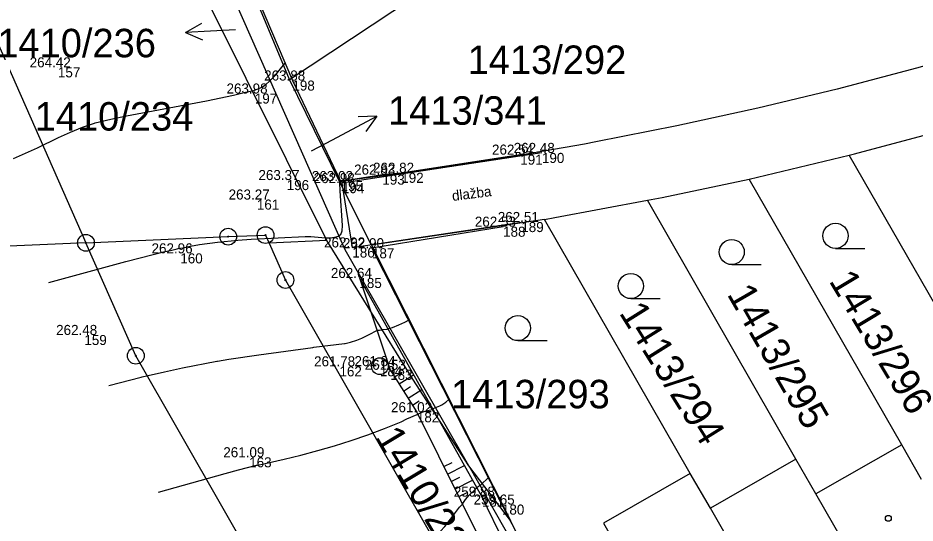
# Model space of a CAD drawing. Extents: x -771260 to -770828, y -1053564 to -1052811.
# Drawn here: x -770918.2 to -770864.6, y -1053347.8 to -1053317.7 of the extents above; entities that cross this region are included whole.
import ezdxf

# ---------------------------------------------------------------- set-up
doc = ezdxf.new("R2010")
doc.units = 0
for name, color, linetype in [('18_8_2023_dlazba', 7, 'Continuous'), ('18_8_2023_plot', 7, 'Continuous'), ('18_8_2023_popis_povrchu', 7, 'Continuous'), ('18_8_2023_sachta', 7, 'Continuous'), ('18_8_2023_ter_hrana', 7, 'Continuous'), ('18_8_2023_ter_pata', 7, 'Continuous'), ('18_8_2023_ter_srafa', 7, 'Continuous'), ('18_8_2023_vrstevnice_po_1m', 7, 'Continuous'), ('18_8_2023_vstup', 7, 'Continuous'), ('18_8_2023_zamereny_bod', 7, 'Continuous'), ('18_8_2023_zamereny_bod_cislo', 7, 'Continuous'), ('18_8_2023_zamereny_bod_vyska', 7, 'Continuous'), ('DKM_Hranice parcel', 7, 'Continuous'), ('DKM_Parcelní čísla', 7, 'Continuous'), ('DKM_Pop  PČ popisy', 7, 'Continuous'), ('DKM_Značky bodu BP', 7, 'Continuous'), ('DKM_Značky budov', 7, 'Continuous'), ('DKM_Značky kultur', 7, 'Continuous')]:
    doc.layers.add(name, color=color, linetype=linetype)

msp = doc.modelspace()

# ---------------------------------------------------------------- linework, layer by layer
at = {"layer": '18_8_2023_dlazba'}
for p, q in [((-770886.844, -1053325.753), (-770898.793, -1053327.556)), ((-770898.793, -1053327.556), (-770898.174, -1053331.397)), ((-770898.174, -1053331.397), (-770888.078, -1053329.878))]:
    msp.add_line(p, q, dxfattribs=at)
at = {"layer": '18_8_2023_plot'}
for p, q in [((-770906.001, -1053311.457), (-770901.756, -1053321.432)), ((-770901.756, -1053321.432), (-770898.876, -1053327.433)), ((-770895.251, -1053326.939), (-770888.14, -1053325.855)), ((-770898.876, -1053327.433), (-770896.381, -1053327.047)), ((-770889.166, -1053330.157), (-770897.001, -1053331.442)), ((-770897.001, -1053331.442), (-770889.236, -1053346.745)), ((-770889.236, -1053346.745), (-770886.57, -1053351.912))]:
    msp.add_line(p, q, dxfattribs=at)
at = {"layer": '18_8_2023_sachta'}
msp.add_circle((-770896.528, -1053338.484), 0.5, dxfattribs=at)
at = {"layer": '18_8_2023_ter_hrana'}
for p, q in [((-770897.752, -1053333.219), (-770895.914, -1053338.7)), ((-770895.914, -1053338.7), (-770894.318, -1053341.233)), ((-770894.318, -1053341.233), (-770889.903, -1053350.127))]:
    msp.add_line(p, q, dxfattribs=at)
at = {"layer": '18_8_2023_ter_pata'}
for p, q in [((-770890.436, -1053346.273), (-770897.752, -1053333.219)), ((-770887.502, -1053352.25), (-770890.436, -1053346.273))]:
    msp.add_line(p, q, dxfattribs=at)
at = {"layer": '18_8_2023_ter_srafa'}
for p, q in [((-770895.647, -1053339.123), (-770895.202, -1053338.842)), ((-770895.38, -1053339.546), (-770894.512, -1053338.998)), ((-770895.114, -1053339.969), (-770894.691, -1053339.702)), ((-770894.847, -1053340.392), (-770894.023, -1053339.872)), ((-770894.581, -1053340.815), (-770894.179, -1053340.562)), ((-770892.709, -1053344.474), (-770892.214, -1053344.228)), ((-770892.486, -1053344.921), (-770891.474, -1053344.419)), ((-770892.264, -1053345.369), (-770891.747, -1053345.112)), ((-770892.042, -1053345.817), (-770890.985, -1053345.292)), ((-770891.819, -1053346.265), (-770891.28, -1053345.997))]:
    msp.add_line(p, q, dxfattribs=at)
at = {"layer": '18_8_2023_vrstevnice_po_1m'}
for points in [[(-770918.418, -1053326.093), (-770916.989, -1053325.442), (-770915.723, -1053324.835), (-770915.014, -1053324.51), (-770914.29, -1053324.207), (-770913.573, -1053323.975), (-770913.53, -1053323.961), (-770912.601, -1053323.74), (-770911.658, -1053323.542), (-770906.885, -1053322.637), (-770905.279, -1053322.303), (-770904.551, -1053322.134), (-770904.054, -1053322.018), (-770904.016, -1053322.009), (-770903.792, -1053321.933), (-770903.577, -1053321.823), (-770903.37, -1053321.683), (-770903.105, -1053321.455), (-770902.944, -1053321.296), (-770902.789, -1053321.129), (-770902.382, -1053320.627), (-770902.196, -1053320.399), (-770902.166, -1053320.362)], [(-770902.166, -1053320.362), (-770902.166, -1053320.362)], [(-770902.166, -1053320.362), (-770902.166, -1053320.362)], [(-770902.944, -1053321.296), (-770902.944, -1053321.296)], [(-770902.789, -1053321.129), (-770902.789, -1053321.129)], [(-770903.577, -1053321.823), (-770903.577, -1053321.823)], [(-770903.37, -1053321.683), (-770903.37, -1053321.683)], [(-770903.105, -1053321.455), (-770903.105, -1053321.455)], [(-770905.279, -1053322.303), (-770905.279, -1053322.303)], [(-770904.016, -1053322.009), (-770904.016, -1053322.009)], [(-770903.792, -1053321.933), (-770903.792, -1053321.933)], [(-770906.885, -1053322.637), (-770906.885, -1053322.637)], [(-770913.53, -1053323.961), (-770913.53, -1053323.961)], [(-770912.601, -1053323.74), (-770912.601, -1053323.74)], [(-770911.658, -1053323.542), (-770911.658, -1053323.542)], [(-770915.014, -1053324.51), (-770915.014, -1053324.51)], [(-770914.29, -1053324.207), (-770914.29, -1053324.207)], [(-770915.723, -1053324.835), (-770915.723, -1053324.835)], [(-770916.989, -1053325.442), (-770916.989, -1053325.442)], [(-770916.308, -1053333.484), (-770911.709, -1053332.232), (-770910.077, -1053331.813), (-770909.381, -1053331.646), (-770909.044, -1053331.574), (-770908.962, -1053331.557), (-770908.632, -1053331.477), (-770908.586, -1053331.466), (-770908.295, -1053331.409), (-770907.864, -1053331.324), (-770907.844, -1053331.32), (-770907.303, -1053331.229), (-770906.237, -1053331.08), (-770905.015, -1053330.965), (-770904.21, -1053330.91), (-770900.991, -1053330.743), (-770900.922, -1053330.739), (-770900.661, -1053330.746), (-770899.782, -1053330.817), (-770899.448, -1053330.817), (-770899.35, -1053330.807), (-770899.27, -1053330.799), (-770899.024, -1053330.717), (-770898.908, -1053330.644), (-770898.87, -1053330.619), (-770898.775, -1053330.395), (-770898.769, -1053330.082), (-770898.909, -1053328.014), (-770898.929, -1053327.548), (-770898.931, -1053327.514), (-770898.901, -1053327.492), (-770898.846, -1053327.477), (-770898.802, -1053327.464), (-770898.657, -1053327.399), (-770898.562, -1053327.357)], [(-770898.931, -1053327.514), (-770898.931, -1053327.514)], [(-770898.901, -1053327.492), (-770898.901, -1053327.492)], [(-770898.802, -1053327.464), (-770898.802, -1053327.464)], [(-770898.909, -1053328.014), (-770898.909, -1053328.014)], [(-770898.775, -1053330.395), (-770898.775, -1053330.395)], [(-770898.769, -1053330.082), (-770898.769, -1053330.082)], [(-770905.015, -1053330.965), (-770905.015, -1053330.965)], [(-770904.21, -1053330.91), (-770904.21, -1053330.91)], [(-770900.922, -1053330.739), (-770900.922, -1053330.739)], [(-770900.661, -1053330.746), (-770900.661, -1053330.746)], [(-770899.782, -1053330.817), (-770899.782, -1053330.817)], [(-770899.448, -1053330.817), (-770899.448, -1053330.817)], [(-770899.27, -1053330.799), (-770899.27, -1053330.799)], [(-770899.024, -1053330.717), (-770899.024, -1053330.717)], [(-770898.87, -1053330.619), (-770898.87, -1053330.619)], [(-770908.586, -1053331.466), (-770908.586, -1053331.466)], [(-770907.864, -1053331.324), (-770907.864, -1053331.324)], [(-770907.303, -1053331.229), (-770907.303, -1053331.229)], [(-770906.237, -1053331.08), (-770906.237, -1053331.08)], [(-770910.077, -1053331.813), (-770910.077, -1053331.813)], [(-770909.381, -1053331.646), (-770909.381, -1053331.646)], [(-770908.962, -1053331.557), (-770908.962, -1053331.557)], [(-770911.709, -1053332.232), (-770911.709, -1053332.232)], [(-770916.308, -1053333.484), (-770916.308, -1053333.484)], [(-770912.725, -1053339.643), (-770910.784, -1053339.142), (-770910.728, -1053339.128), (-770909.401, -1053338.818), (-770908.314, -1053338.582), (-770906.273, -1053338.194), (-770906.234, -1053338.186), (-770905.55, -1053338.07), (-770903.757, -1053337.801), (-770900.54, -1053337.361), (-770900.476, -1053337.353), (-770898.633, -1053337.127), (-770898.609, -1053337.124), (-770898.286, -1053337.055), (-770897.896, -1053336.924), (-770897.616, -1053336.81), (-770897.169, -1053336.599), (-770896.7, -1053336.356), (-770896.664, -1053336.338), (-770896.547, -1053336.331), (-770896.43, -1053336.305), (-770896.389, -1053336.296), (-770896.096, -1053336.274), (-770896.049, -1053336.257), (-770896.008, -1053336.242), (-770895.782, -1053336.178), (-770895.388, -1053336.025), (-770895.044, -1053335.864), (-770895.006, -1053335.846), (-770894.823, -1053335.734), (-770894.787, -1053335.712)], [(-770894.787, -1053335.712), (-770894.787, -1053335.712)], [(-770894.787, -1053335.712), (-770894.787, -1053335.712)], [(-770896.664, -1053336.338), (-770896.664, -1053336.338)], [(-770896.547, -1053336.331), (-770896.547, -1053336.331)], [(-770896.389, -1053336.296), (-770896.389, -1053336.296)], [(-770896.096, -1053336.274), (-770896.096, -1053336.274)], [(-770896.008, -1053336.242), (-770896.008, -1053336.242)], [(-770895.782, -1053336.178), (-770895.782, -1053336.178)], [(-770895.388, -1053336.025), (-770895.388, -1053336.025)], [(-770895.006, -1053335.846), (-770895.006, -1053335.846)], [(-770897.616, -1053336.81), (-770897.616, -1053336.81)], [(-770897.169, -1053336.599), (-770897.169, -1053336.599)], [(-770900.476, -1053337.353), (-770900.476, -1053337.353)], [(-770898.609, -1053337.124), (-770898.609, -1053337.124)], [(-770898.286, -1053337.055), (-770898.286, -1053337.055)], [(-770897.896, -1053336.924), (-770897.896, -1053336.924)], [(-770903.757, -1053337.801), (-770903.757, -1053337.801)], [(-770906.234, -1053338.186), (-770906.234, -1053338.186)], [(-770905.55, -1053338.07), (-770905.55, -1053338.07)], [(-770909.401, -1053338.818), (-770909.401, -1053338.818)], [(-770908.314, -1053338.582), (-770908.314, -1053338.582)], [(-770910.728, -1053339.128), (-770910.728, -1053339.128)], [(-770912.725, -1053339.643), (-770912.725, -1053339.643)], [(-770909.747, -1053346.007), (-770905.768, -1053344.887), (-770904.974, -1053344.681), (-770903.897, -1053344.402), (-770903.848, -1053344.389), (-770903.453, -1053344.31), (-770903.38, -1053344.296), (-770902.25, -1053344.038), (-770901.247, -1053343.79), (-770900.245, -1053343.524), (-770899.245, -1053343.235), (-770898.246, -1053342.92), (-770897.25, -1053342.578), (-770896.256, -1053342.205), (-770895.264, -1053341.8), (-770894.911, -1053341.635), (-770894.307, -1053341.377), (-770894.275, -1053341.363), (-770894.258, -1053341.354), (-770894.235, -1053341.341), (-770894.221, -1053341.334), (-770893.996, -1053341.223), (-770893.771, -1053341.159), (-770893.474, -1053341.088), (-770893.412, -1053341.063), (-770893.37, -1053341.037), (-770893.334, -1053341.015), (-770892.945, -1053340.85), (-770892.857, -1053340.803), (-770892.821, -1053340.783), (-770892.594, -1053340.624), (-770892.415, -1053340.48), (-770892.381, -1053340.453)], [(-770892.594, -1053340.624), (-770892.594, -1053340.624)], [(-770892.381, -1053340.453), (-770892.381, -1053340.453)], [(-770892.381, -1053340.453), (-770892.381, -1053340.453)], [(-770893.771, -1053341.159), (-770893.771, -1053341.159)], [(-770893.474, -1053341.088), (-770893.474, -1053341.088)], [(-770893.412, -1053341.063), (-770893.412, -1053341.063)], [(-770893.334, -1053341.015), (-770893.334, -1053341.015)], [(-770892.945, -1053340.85), (-770892.945, -1053340.85)], [(-770892.821, -1053340.783), (-770892.821, -1053340.783)], [(-770894.911, -1053341.635), (-770894.911, -1053341.635)], [(-770894.275, -1053341.363), (-770894.275, -1053341.363)], [(-770894.221, -1053341.334), (-770894.221, -1053341.334)], [(-770893.996, -1053341.223), (-770893.996, -1053341.223)], [(-770896.256, -1053342.205), (-770896.256, -1053342.205)], [(-770895.264, -1053341.8), (-770895.264, -1053341.8)], [(-770897.25, -1053342.578), (-770897.25, -1053342.578)], [(-770899.245, -1053343.235), (-770899.245, -1053343.235)], [(-770898.246, -1053342.92), (-770898.246, -1053342.92)], [(-770901.247, -1053343.79), (-770901.247, -1053343.79)], [(-770900.245, -1053343.524), (-770900.245, -1053343.524)], [(-770903.38, -1053344.296), (-770903.38, -1053344.296)], [(-770902.25, -1053344.038), (-770902.25, -1053344.038)], [(-770905.768, -1053344.887), (-770905.768, -1053344.887)], [(-770903.848, -1053344.389), (-770903.848, -1053344.389)], [(-770893.346, -1053348.689), (-770893.123, -1053348.53), (-770892.909, -1053348.337), (-770892.651, -1053348.052), (-770892.308, -1053347.623), (-770891.763, -1053346.908), (-770891.597, -1053346.714), (-770891.567, -1053346.679), (-770891.408, -1053346.444), (-770891.186, -1053346.175), (-770890.801, -1053345.799), (-770890.737, -1053345.736), (-770890.705, -1053345.705), (-770890.691, -1053345.697), (-770890.655, -1053345.676), (-770890.472, -1053345.54), (-770890.049, -1053345.143), (-770890.017, -1053345.112)], [(-770890.017, -1053345.112), (-770890.017, -1053345.112)], [(-770890.017, -1053345.112), (-770890.017, -1053345.112)], [(-770890.705, -1053345.705), (-770890.705, -1053345.705)], [(-770890.655, -1053345.676), (-770890.655, -1053345.676)], [(-770890.472, -1053345.54), (-770890.472, -1053345.54)], [(-770909.747, -1053346.007), (-770909.747, -1053346.007)], [(-770891.408, -1053346.444), (-770891.408, -1053346.444)], [(-770891.186, -1053346.175), (-770891.186, -1053346.175)], [(-770891.763, -1053346.908), (-770891.763, -1053346.908)], [(-770891.567, -1053346.679), (-770891.567, -1053346.679)], [(-770892.308, -1053347.623), (-770892.308, -1053347.623)]]:
    msp.add_lwpolyline(points, dxfattribs=at)
at = {"layer": '18_8_2023_vstup'}
msp.add_line((-770896.381, -1053327.047), (-770895.251, -1053326.939), dxfattribs=at)
at = {"layer": '18_8_2023_zamereny_bod'}
for p, q in [((-770915.766, -1053320.645), (-770915.766, -1053320.645)), ((-770901.756, -1053321.432), (-770901.756, -1053321.432)), ((-770904, -1053322.207), (-770904, -1053322.207)), ((-770888.14, -1053325.855), (-770888.14, -1053325.855)), ((-770886.844, -1053325.753), (-770886.844, -1053325.753)), ((-770896.381, -1053327.047), (-770896.381, -1053327.047)), ((-770895.251, -1053326.939), (-770895.251, -1053326.939)), ((-770902.096, -1053327.373), (-770902.096, -1053327.373)), ((-770898.876, -1053327.433), (-770898.876, -1053327.433)), ((-770898.793, -1053327.556), (-770898.793, -1053327.556)), ((-770903.878, -1053328.536), (-770903.878, -1053328.536)), ((-770888.078, -1053329.878), (-770888.078, -1053329.878)), ((-770889.166, -1053330.157), (-770889.166, -1053330.157)), ((-770898.174, -1053331.397), (-770898.174, -1053331.397)), ((-770897.001, -1053331.442), (-770897.001, -1053331.442)), ((-770908.453, -1053331.748), (-770908.453, -1053331.748)), ((-770897.752, -1053333.219), (-770897.752, -1053333.219)), ((-770914.185, -1053336.621), (-770914.185, -1053336.621)), ((-770896.528, -1053338.484), (-770896.528, -1053338.484)), ((-770898.942, -1053338.495), (-770898.942, -1053338.495)), ((-770895.914, -1053338.7), (-770895.914, -1053338.7)), ((-770894.318, -1053341.233), (-770894.318, -1053341.233)), ((-770904.336, -1053343.922), (-770904.336, -1053343.922)), ((-770890.436, -1053346.273), (-770890.436, -1053346.273)), ((-770889.236, -1053346.745), (-770889.236, -1053346.745))]:
    msp.add_line(p, q, dxfattribs=at)
at = {"layer": 'DKM_Hranice parcel'}
for p, q in [((-770901.92, -1053321.36), (-770881.08, -1053307.59)), ((-770923.33, -1053310.27), (-770914.09, -1053331.12)), ((-770898.6, -1053331.53), (-770907.38, -1053311.7)), ((-770901.92, -1053321.36), (-770905.89, -1053311.84)), ((-770899.69, -1053330.99), (-770908.06, -1053314.19)), ((-770898.94, -1053327.46), (-770901.92, -1053321.36)), ((-770874.47, -1053327.31), (-770868.48, -1053325.89)), ((-770859.04, -1053342.32), (-770868.48, -1053325.89)), ((-770897.03, -1053331.25), (-770898.94, -1053327.46)), ((-770865.35, -1053343.17), (-770874.47, -1053327.31)), ((-770871.67, -1053344.03), (-770880.53, -1053328.58)), ((-770886.69, -1053329.72), (-770897.03, -1053331.25)), ((-770877.98, -1053344.89), (-770886.69, -1053329.72)), ((-770903.36, -1053330.66), (-770903.14, -1053331.15)), ((-770899.69, -1053330.99), (-770903.14, -1053331.15)), ((-770903.14, -1053331.15), (-770902.17, -1053333.34)), ((-770897.03, -1053331.25), (-770888.72, -1053347.69)), ((-770891.21, -1053344.44), (-770898.6, -1053331.53)), ((-770865.35, -1053343.17), (-770870.47, -1053346.11)), ((-770864.16, -1053345.25), (-770865.35, -1053343.17)), ((-770871.67, -1053344.03), (-770876.78, -1053346.97)), ((-770870.47, -1053346.11), (-770871.67, -1053344.03)), ((-770888.72, -1053347.69), (-770891.21, -1053344.44)), ((-770891.21, -1053344.44), (-770883.99, -1053357.06)), ((-770876.78, -1053346.97), (-770877.98, -1053344.89)), ((-770886.69, -1053351.72), (-770888.72, -1053347.69))]:
    msp.add_line(p, q, dxfattribs=at)
for points in [[(-770849.65, -1053316.11), (-770854.288, -1053317.659), (-770858.956, -1053319.113), (-770859.765, -1053319.355), (-770864.468, -1053320.696), (-770869.196, -1053321.942), (-770873.95, -1053323.09), (-770878.776, -1053324.144), (-770883.621, -1053325.1), (-770884.295, -1053325.225), (-770889.162, -1053326.069), (-770894.044, -1053326.814), (-770898.94, -1053327.46)], [(-770868.48, -1053325.89), (-770868.16, -1053325.81), (-770862.57, -1053324.32)], [(-770880.53, -1053328.58), (-770879.66, -1053328.41), (-770874.47, -1053327.31)], [(-770886.69, -1053329.72), (-770886.07, -1053329.61), (-770880.53, -1053328.58)], [(-770914.09, -1053331.12), (-770905.59, -1053330.75), (-770903.36, -1053330.66)], [(-770914.09, -1053331.12), (-770924.63, -1053331.58), (-770925.69, -1053331.62)], [(-770893.63, -1053367.36), (-770895.54, -1053365.07), (-770911.11, -1053337.86), (-770914.09, -1053331.12)], [(-770891.21, -1053344.44), (-770894.56, -1053339.26), (-770899.69, -1053330.99)], [(-770902.17, -1053333.34), (-770887.29, -1053359.35), (-770881.36, -1053366.49)], [(-770877.98, -1053344.89), (-770883.16, -1053347.86), (-770876.44, -1053359.57), (-770873.05, -1053365.46)], [(-770860.3, -1053363.83), (-770862.54, -1053359.93), (-770863.75, -1053357.82), (-770864.94, -1053355.74), (-770870.47, -1053346.11)], [(-770866.61, -1053364.68), (-770868.29, -1053361.75), (-770870.06, -1053358.67), (-770871.26, -1053356.59), (-770876.78, -1053346.97)]]:
    msp.add_lwpolyline(points, dxfattribs=at)
at = {"layer": 'DKM_Pop  PČ popisy'}
for p, q in [((-770908.147, -1053318.557), (-770907.173, -1053318.005)), ((-770905.15, -1053318.4), (-770908.147, -1053318.557)), ((-770908.147, -1053318.557), (-770907.121, -1053319.005)), ((-770899.36, -1053324.97), (-770896.71, -1053323.561)), ((-770896.71, -1053323.561), (-770897.83, -1053323.589)), ((-770896.71, -1053323.561), (-770897.359, -1053324.473)), ((-770900.61, -1053325.63), (-770899.36, -1053324.97))]:
    msp.add_line(p, q, dxfattribs=at)
at = {"layer": 'DKM_Značky bodu BP'}
for centre, radius in [((-770905.59, -1053330.75), 0.5), ((-770903.36, -1053330.66), 0.5), ((-770914.09, -1053331.12), 0.5), ((-770905.59, -1053330.75), 0.0303), ((-770903.36, -1053330.66), 0.0303), ((-770914.09, -1053331.12), 0.0303), ((-770902.17, -1053333.34), 0.5), ((-770902.17, -1053333.34), 0.0303), ((-770911.11, -1053337.86), 0.5), ((-770911.11, -1053337.86), 0.0303)]:
    msp.add_circle(centre, radius, dxfattribs=at)
at = {"layer": 'DKM_Značky budov'}
msp.add_circle((-770866.147, -1053347.569), 0.175, dxfattribs=at)
at = {"layer": 'DKM_Značky kultur'}
for p, q in [((-770869.303, -1053331.45), (-770867.553, -1053331.45)), ((-770875.503, -1053332.42), (-770873.753, -1053332.42)), ((-770881.533, -1053334.45), (-770879.783, -1053334.45)), ((-770888.283, -1053336.96), (-770886.533, -1053336.96))]:
    msp.add_line(p, q, dxfattribs=at)
for centre in [(-770869.303, -1053330.7), (-770875.503, -1053331.67), (-770881.533, -1053333.7), (-770888.283, -1053336.21)]:
    msp.add_circle(centre, 0.75, dxfattribs=at)

# ---------------------------------------------------------------- texts
at = {"layer": '18_8_2023_popis_povrchu'}
msp.add_text('dlažba', height=0.6, rotation=7.1461, dxfattribs=at).set_placement((-770892.179, -1053328.621))
at = {"layer": '18_8_2023_zamereny_bod_cislo'}
for s, p in [('157', (-770915.766, -1053321.245)), ('198', (-770901.756, -1053322.032)), ('197', (-770904, -1053322.807)), ('191', (-770888.14, -1053326.455)), ('190', (-770886.844, -1053326.353)), ('193', (-770896.381, -1053327.647)), ('192', (-770895.251, -1053327.539)), ('196', (-770902.096, -1053327.973)), ('195', (-770898.876, -1053328.033)), ('194', (-770898.793, -1053328.156)), ('161', (-770903.878, -1053329.136)), ('189', (-770888.078, -1053330.478)), ('188', (-770889.166, -1053330.757)), ('186', (-770898.174, -1053331.997)), ('187', (-770897.001, -1053332.042)), ('160', (-770908.453, -1053332.348)), ('185', (-770897.752, -1053333.819)), ('159', (-770914.185, -1053337.221)), ('162', (-770898.942, -1053339.095)), ('184', (-770896.528, -1053339.084)), ('183', (-770895.914, -1053339.3)), ('182', (-770894.318, -1053341.833)), ('163', (-770904.336, -1053344.522)), ('181', (-770890.436, -1053346.873)), ('180', (-770889.236, -1053347.345))]:
    msp.add_text(s, height=0.6, dxfattribs=at).set_placement(p)
at = {"layer": '18_8_2023_zamereny_bod_vyska'}
for s, p in [('264.42 ', (-770917.454, -1053320.645)), ('263.88 ', (-770903.444, -1053321.432)), ('263.98 ', (-770905.691, -1053322.207)), ('262.54 ', (-770889.828, -1053325.855)), ('262.48 ', (-770888.532, -1053325.753)), ('262.83 ', (-770898.069, -1053327.047)), ('262.82 ', (-770896.939, -1053326.939)), ('263.37 ', (-770903.784, -1053327.373)), ('263.02 ', (-770900.59, -1053327.433)), ('262.98 ', (-770900.484, -1053327.556)), ('263.27 ', (-770905.566, -1053328.536)), ('262.51 ', (-770889.483, -1053329.878)), ('262.53 ', (-770890.854, -1053330.157)), ('262.92 ', (-770899.865, -1053331.397)), ('262.90 ', (-770898.735, -1053331.442)), ('262.96 ', (-770910.171, -1053331.748)), ('262.64 ', (-770899.457, -1053333.219)), ('262.48 ', (-770915.873, -1053336.621)), ('261.78 ', (-770900.46, -1053338.495)), ('261.84 ', (-770898.046, -1053338.484)), ('261.53 ', (-770897.432, -1053338.7)), ('261.02 ', (-770895.862, -1053341.233)), ('261.09 ', (-770905.884, -1053343.922)), ('259.88 ', (-770892.11, -1053346.273)), ('259.65 ', (-770890.927, -1053346.745))]:
    msp.add_text(s, height=0.6, dxfattribs=at).set_placement(p)
at = {"layer": 'DKM_Parcelní čísla'}
for s, p in [('1410/236', (-770919.391, -1053320.044)), ('1413/292', (-770891.285, -1053321.04)), ('1413/341', (-770896.04, -1053324.07)), ('1410/234', (-770917.155, -1053324.42)), ('1413/293', (-770892.275, -1053340.999))]:
    msp.add_text(s, height=1.7, dxfattribs=at).set_placement(p)
for s, rotation, p in [('1413/296', 301, (-770869.73, -1053333.391)), ('1413/295', 300, (-770875.819, -1053334.181)), ('1413/294', 302, (-770882.27, -1053335.301)), ('1410/226', 301, (-770896.86, -1053342.711))]:
    msp.add_text(s, height=1.7, rotation=rotation, dxfattribs=at).set_placement(p)

doc.saveas('drawing.dxf')
